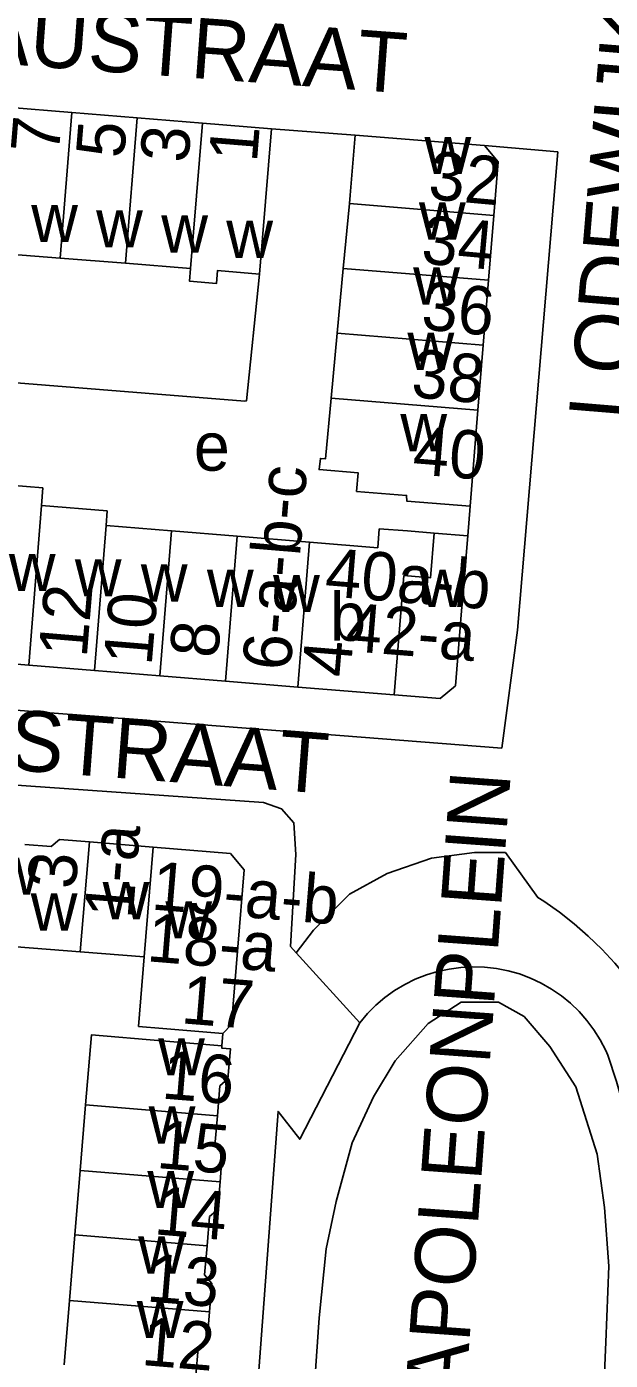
# Model space of a CAD drawing. Extents: x 159261 to 160849, y 382514 to 384534.
# Drawn here: x 160539 to 160587.3, y 383087.7 to 383197.9 of the extents above; entities that cross this region are included whole.
import ezdxf

# ---------------------------------------------------------------- set-up
doc = ezdxf.new("R2010")
doc.units = 0
for name, color, linetype in [('BLT_Basislijn', 7, 'Continuous'), ('BLT_Bebouwing', 7, 'Continuous'), ('BLT_Centroide', 7, 'Continuous'), ('BLT_Huisnummer', 7, 'Continuous'), ('BLT_Huisnummer_ tussenligend', 7, 'Continuous'), ('BLT_Huisnummer_reeks', 7, 'Continuous'), ('BLT_Onderverdeling_panden', 7, 'Continuous'), ('BLT_Straatnaam', 7, 'Continuous')]:
    doc.layers.add(name, color=color, linetype=linetype)

msp = doc.modelspace()

# ---------------------------------------------------------------- linework, layer by layer
at = {"layer": 'BLT_Basislijn'}
for p, q in [((160559.24, 383189.51), (160566.16, 383188.98)), ((160576.87, 383188.11), (160582.94, 383187.6)), ((160575.48, 383155.85), (160575.68, 383158.3)), ((160561.28, 383121.37), (160566.55, 383115.58))]:
    msp.add_line(p, q, dxfattribs=at)
for points in [[(160582.94, 383187.6), (160579.6, 383148.05), (160578.31, 383138.29)], [(160558.27, 383177.49), (160557.19, 383167.01), (160557.03, 383166.97), (160500, 383171.55), (160470.63, 383174.29)], [(160578.31, 383138.29), (160500, 383144.4), (160454.31, 383148.99), (160451.84, 383149.54), (160450.64, 383150.64), (160449.77, 383151.95), (160449.76, 383153.4)], [(160561.28, 383121.37), (160560.81, 383121.89), (160561.25, 383129.5), (160561.1, 383132.1), (160560.08, 383133.27), (160558.59, 383133.79), (160513.39, 383136.96), (160512.75, 383137)], [(160578.61, 383129.65), (160576.04, 383129.65), (160572.5, 383129.19), (160568.82, 383127.92), (160565.7, 383126.22), (160562.73, 383123.24), (160561.28, 383121.37)], [(160578.61, 383129.65), (160581.28, 383125.93), (160581.79, 383125.63)], [(160581.79, 383125.63), (160583.07, 383124.73), (160584.29, 383123.76), (160585.46, 383122.73), (160586.58, 383121.65), (160587.65, 383120.5), (160588.65, 383119.31), (160589.59, 383118.06), (160590.46, 383116.77), (160591.27, 383115.43), (160592.01, 383114.06), (160592.68, 383112.65), (160593.27, 383111.2), (160593.79, 383109.73), (160594.23, 383108.23), (160594.6, 383106.72), (160594.88, 383105.18), (160595.04, 383104.06)], [(160566.55, 383115.58), (160567.19, 383116.33), (160567.88, 383117.02), (160568.63, 383117.66), (160569.42, 383118.23), (160570.27, 383118.73), (160571.14, 383119.17), (160572.06, 383119.53), (160572.99, 383119.82), (160573.95, 383120.02), (160574.92, 383120.15), (160575.9, 383120.2), (160576.88, 383120.17), (160577.86, 383120.06), (160578.82, 383119.87), (160579.76, 383119.61), (160580.68, 383119.26), (160581.57, 383118.85), (160582.42, 383118.36), (160583.23, 383117.81), (160583.99, 383117.19), (160584.7, 383116.51), (160585.35, 383115.77), (160585.93, 383114.99), (160586.45, 383114.16), (160586.91, 383113.29), (160587.08, 383112.9)], [(160562.71, 383084.05), (160563.19, 383091.18), (160563.78, 383096.87), (160564.61, 383100.79), (160565.92, 383105.66), (160567.7, 383109.45), (160569.48, 383112.42), (160572.2, 383115.51), (160574.93, 383117.29), (160578.02, 383117.29), (160580.15, 383116.1), (160582.29, 383113.61), (160584.42, 383110.28), (160586.2, 383104.71), (160586.79, 383100.31), (160587.15, 383095.45), (160586.91, 383089.16), (160586.68, 383084.05)], [(160566.55, 383115.58), (160561.59, 383105.95), (160559.79, 383108.24), (160558.01, 383084.24), (160557.16, 383074.29), (160556.55, 383069.51), (160555.78, 383069.02)], [(160587.08, 383112.9), (160587.8, 383110.71), (160588.44, 383108.5), (160589, 383106.27), (160589.48, 383104.02), (160589.89, 383101.75), (160590.21, 383099.48), (160590.46, 383097.19), (160590.63, 383094.89), (160590.72, 383092.59), (160590.72, 383090.29), (160590.65, 383087.99), (160590.5, 383085.7), (160590.27, 383083.41), (160589.96, 383081.13), (160589.57, 383078.86), (160589.1, 383076.61), (160588.55, 383074.37), (160587.93, 383072.16), (160587.29, 383070.02), (160586.62, 383067.83), (160586.1, 383066.26)]]:
    msp.add_lwpolyline(points, dxfattribs=at)
at = {"layer": 'BLT_Bebouwing'}
for p, q in [((160537.34, 383191.28), (160542.74, 383190.84)), ((160542.74, 383190.84), (160548.14, 383190.41)), ((160548.14, 383190.41), (160553.54, 383189.97)), ((160553.54, 383189.97), (160559.24, 383189.51)), ((160559.24, 383189.51), (160558.27, 383177.49)), ((160576.87, 383188.11), (160566.16, 383188.98)), ((160565.7, 383183.32), (160565.19, 383177.95)), ((160577.2, 383176.97), (160577.64, 383182.34)), ((160536.36, 383179.24), (160541.76, 383178.81)), ((160541.76, 383178.81), (160547.16, 383178.38)), ((160547.16, 383178.38), (160552.56, 383177.95)), ((160565.19, 383177.95), (160564.69, 383172.59)), ((160576.76, 383171.6), (160577.2, 383176.97)), ((160564.69, 383172.59), (160564.19, 383167.22)), ((160576.32, 383166.23), (160576.76, 383171.6)), ((160545.56, 383156.7), (160550.98, 383156.25)), ((160550.98, 383156.25), (160556.41, 383155.81)), ((160556.41, 383155.81), (160562.39, 383155.32)), ((160572.71, 383156.07), (160575.48, 383155.85)), ((160562.39, 383155.32), (160568.04, 383154.86)), ((160533.74, 383145.58), (160539.17, 383145.14)), ((160539.17, 383145.14), (160544.6, 383144.7)), ((160544.6, 383144.7), (160550.02, 383144.26)), ((160550.02, 383144.26), (160555.45, 383143.82)), ((160555.45, 383143.82), (160561.43, 383143.33)), ((160561.43, 383143.33), (160569.4, 383142.69)), ((160538.16, 383121.85), (160543.43, 383121.43)), ((160543.43, 383121.43), (160548.71, 383121.02)), ((160548.71, 383121.02), (160548.24, 383115.27)), ((160555.15, 383113.67), (160555.23, 383114.69)), ((160543.87, 383108.78), (160543.42, 383103.36)), ((160543.42, 383103.36), (160542.98, 383098.05)), ((160542.98, 383098.05), (160542.53, 383092.62)), ((160542.53, 383092.62), (160542.09, 383087.3))]:
    msp.add_line(p, q, dxfattribs=at)
for points in [[(160566.16, 383188.98), (160565.76, 383184), (160565.7, 383183.32)], [(160577.64, 383182.34), (160578, 383186.78), (160576.87, 383188.11)], [(160552.56, 383177.95), (160552.47, 383176.89), (160554.7, 383176.72), (160554.78, 383177.77), (160558.27, 383177.49)], [(160564.19, 383167.22), (160563.72, 383162.21), (160563.29, 383162.24), (160563.19, 383161.32), (160566.42, 383161.04), (160566.29, 383159.51), (160570.43, 383159.18), (160570.44, 383158.72), (160575.68, 383158.3)], [(160575.68, 383158.3), (160576.32, 383166.23)], [(160534.7, 383157.58), (160534.91, 383160.25), (160540.33, 383159.81), (160540.22, 383158.35)], [(160540.22, 383158.35), (160545.65, 383157.9), (160545.56, 383156.7)], [(160568.04, 383154.86), (160568.17, 383156.41), (160570.49, 383156.25), (160572.71, 383156.07)], [(160575.48, 383155.85), (160574.98, 383149.65)], [(160569.4, 383142.69), (160573.21, 383142.38), (160574.47, 383143.45), (160574.98, 383149.65)], [(160544.18, 383130.53), (160541.72, 383130.73), (160541.03, 383130.15), (160538.85, 383130.33)], [(160549.45, 383130.1), (160544.18, 383130.53)], [(160556.46, 383121.82), (160556.99, 383128.23), (160555.85, 383129.57), (160549.45, 383130.1)], [(160555.23, 383114.69), (160555.94, 383115.42), (160556.46, 383121.82)], [(160555.15, 383113.67), (160550.17, 383114.09), (160544.35, 383114.57), (160543.87, 383108.78)], [(160548.24, 383115.27), (160550.25, 383115.1), (160555.23, 383114.69)], [(160555.15, 383113.67), (160555.13, 383113.48), (160555.85, 383113.42), (160555.65, 383110.94), (160554.97, 383110.36), (160554.77, 383107.89)], [(160554.77, 383107.89), (160554.56, 383105.42), (160555.18, 383104.7), (160554.99, 383102.42)], [(160554.99, 383102.42), (160554.8, 383100.13), (160554.12, 383099.55), (160553.92, 383097.14)], [(160553.92, 383097.14), (160553.71, 383094.73), (160554.32, 383094.02), (160554.12, 383091.66)], [(160554.12, 383091.66), (160553.93, 383089.31), (160553.18, 383088.67), (160552.99, 383086.4)]]:
    msp.add_lwpolyline(points, dxfattribs=at)
at = {"layer": 'BLT_Onderverdeling_panden'}
for p, q in [((160541.76, 383178.81), (160542.74, 383190.84)), ((160547.16, 383178.38), (160548.14, 383190.41)), ((160552.56, 383177.95), (160553.54, 383189.97)), ((160565.7, 383183.32), (160577.64, 383182.34)), ((160565.19, 383177.95), (160577.2, 383176.97)), ((160564.69, 383172.59), (160576.76, 383171.6)), ((160564.19, 383167.22), (160576.32, 383166.23)), ((160539.17, 383145.14), (160540.22, 383158.35)), ((160544.6, 383144.7), (160545.56, 383156.7)), ((160550.02, 383144.26), (160550.98, 383156.25)), ((160555.45, 383143.82), (160556.41, 383155.81)), ((160561.43, 383143.33), (160562.39, 383155.32)), ((160544.18, 383130.53), (160543.43, 383121.43)), ((160549.45, 383130.1), (160548.71, 383121.02)), ((160554.77, 383107.89), (160543.87, 383108.78)), ((160554.99, 383102.42), (160543.42, 383103.36)), ((160553.92, 383097.14), (160542.98, 383098.05)), ((160554.12, 383091.66), (160542.53, 383092.62))]:
    msp.add_line(p, q, dxfattribs=at)
msp.add_lwpolyline([(160569.4, 383142.69), (160570.2, 383152.55), (160572.41, 383152.37), (160572.71, 383156.07)], dxfattribs=at)

# ---------------------------------------------------------------- texts
at = {"layer": 'BLT_Centroide'}
for s, p in [('w', (160571.91, 383185.75)), ('w', (160539.37, 383180.13)), ('w', (160571.45, 383180.34)), ('w', (160544.74, 383179.69)), ('w', (160550.13, 383179.26)), ('w', (160555.51, 383178.82)), ('w', (160570.97, 383174.97)), ('w', (160570.5, 383169.56)), ('w', (160569.91, 383162.84)), ('e', (160552.83, 383161.23)), ('w', (160537.52, 383151.28)), ('w', (160542.98, 383150.84)), ('w', (160548.44, 383150.41)), ('w', (160553.91, 383149.97)), ('w', (160559.38, 383149.53)), ('w', (160571.47, 383149.97)), ('b', (160564.1, 383147.16)), ('w', (160536.19, 383126.16)), ('w', (160545.28, 383124.14)), ('w', (160539.33, 383123.2)), ('w', (160550.47, 383122.55)), ('w', (160549.87, 383111.22)), ('w', (160549.09, 383105.59)), ('w', (160548.98, 383100.25)), ('w', (160548.22, 383094.84)), ('w', (160548.1, 383089.5))]:
    msp.add_text(s, height=4, dxfattribs=at).set_placement(p)
at = {"layer": 'BLT_Huisnummer'}
for s, rotation, p in [('5', 85.2991, (160547.04, 383187)), ('1', 85.3763, (160558.04, 383186.67)), ('32', 354.8167, (160572.14, 383183.7)), ('36', 354.6556, (160571.56, 383172.93)), ('40', 355.3739, (160570.85, 383160.95)), ('10', 85.2555, (160549.33, 383145.05)), ('3', 85.3226, (160543.04, 383126.56)), ('16', 355.3122, (160550.09, 383109.32)), ('15', 355.2446, (160549.67, 383103.57)), ('14', 355.2531, (160549.47, 383098.09)), ('13', 355.2576, (160548.85, 383092.54)), ('12', 355.2576, (160548.42, 383087.28))]:
    msp.add_text(s, height=4, rotation=rotation, dxfattribs=at).set_placement(p)
at = {"layer": 'BLT_Huisnummer_ tussenligend'}
for s, rotation, p in [('7', 85.2991, (160541.65, 383187.37)), ('3', 85.3763, (160552.36, 383186.62)), ('34', 354.8167, (160571.56, 383178.38)), ('38', 354.6556, (160570.73, 383167.33)), ('12', 85.2555, (160543.96, 383145.71)), ('8', 85.2558, (160554.81, 383145.66))]:
    msp.add_text(s, height=4, rotation=rotation, dxfattribs=at).set_placement(p)
at = {"layer": 'BLT_Huisnummer_reeks'}
for s, rotation, p in [('6-a-b-c', 85.2573, (160560.81, 383144.62)), ('40a-b', 355.3757, (160563.59, 383150.86)), ('42-a', 355.3877, (160565.3, 383146.34)), ('4', 85.2573, (160565.76, 383144.07)), ('1-a', 85.3201, (160547.76, 383124.11)), ('19-a-b', 355.3094, (160549.24, 383124.95)), ('18-a', 355.3199, (160548.86, 383120.67)), ('17', 355.3077, (160551.7, 383115.54))]:
    msp.add_text(s, height=4, rotation=rotation, dxfattribs=at).set_placement(p)
at = {"layer": 'BLT_Straatnaam'}
for s, height, rotation, p in [('LODEWIJK NAPOLEONLAAN', 5, 85.2642, (160588.82, 383165.33)), ('ALBERTINA VAN NASSAUSTRAAT', 4.9999, 355.7977, (160462.06, 383200.37)), ('AMALIA VAN ANHALTSTRAAT', 5, 355.6341, (160469.29, 383141.72)), ('LODEWIJK NAPOLEONPLEIN', 5, 85.829, (160572.32, 383043.89))]:
    msp.add_text(s, height=height, rotation=rotation, dxfattribs=at).set_placement(p)

doc.saveas('drawing.dxf')
